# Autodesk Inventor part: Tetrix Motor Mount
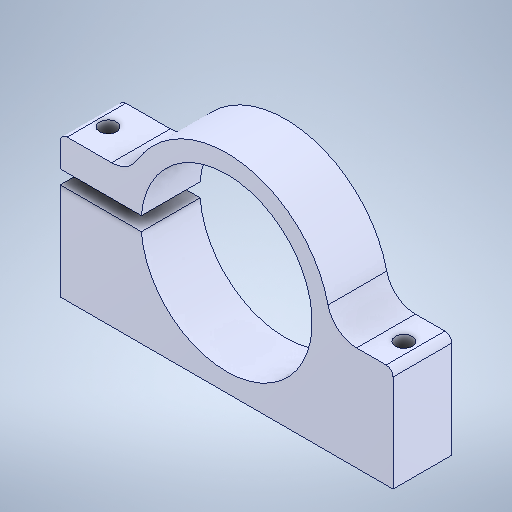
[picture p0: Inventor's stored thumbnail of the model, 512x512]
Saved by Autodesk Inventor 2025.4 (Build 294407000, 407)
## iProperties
Created: 2021-10
Part Number: Tetrix Motor Mount
Material: Genérico
Document SubType Name: Modeling
Designer: usuario
Density: 1 g/cm^3
Appearance: Valor por defecto
Author: usuario
Sending System: SolidWorks 2016
Last Author: LENOVO
Last Saved: 2021-10-22
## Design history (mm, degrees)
fillet "Fillet2"
node "Plane1"
node "Plane2"
node "Sólido1"
